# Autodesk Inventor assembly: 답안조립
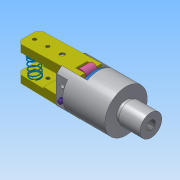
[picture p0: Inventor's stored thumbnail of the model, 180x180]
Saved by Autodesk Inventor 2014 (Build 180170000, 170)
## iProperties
Created: 2019-02
Part Number: 답안조립
Document SubType Name: Assembly
Designer: net
Author: net
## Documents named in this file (11)
- C:\Users\net\Desktop\490207V1008\답안조립.iam
- C:\Users\net\Desktop\490207V1008\E-링.ipt
- C:\Users\net\Desktop\490207V1008\O-링.ipt
- C:\Users\net\Desktop\490207V1008\가이드핀.ipt
- C:\Users\net\Desktop\490207V1008\본체.ipt
- C:\Users\net\Desktop\490207V1008\부시.ipt
- C:\Users\net\Desktop\490207V1008\스프링.ipt
- C:\Users\net\Desktop\490207V1008\평행핀 6x28.ipt
- C:\Users\net\Desktop\490207V1008\피스톤.ipt
- C:\Users\net\Desktop\490207V1008\핀.ipt
- C:\Users\net\Desktop\490207V1008\핑거.ipt
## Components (10 placed, 6 different names)
1. E-링:1
2. O-링:1
3. 가이드핀:1
4. 피스톤:1
5. 핀:1
6. 핑거:1
7. E-링:2
8. 가이드핀:2
9. 핑거:2
10. O-링:2
## Named parameters: d12_d2 = 0, d13_d3 = 0, d14_d4 = 0, d21_d11 = 0, d22_d1 = 0
